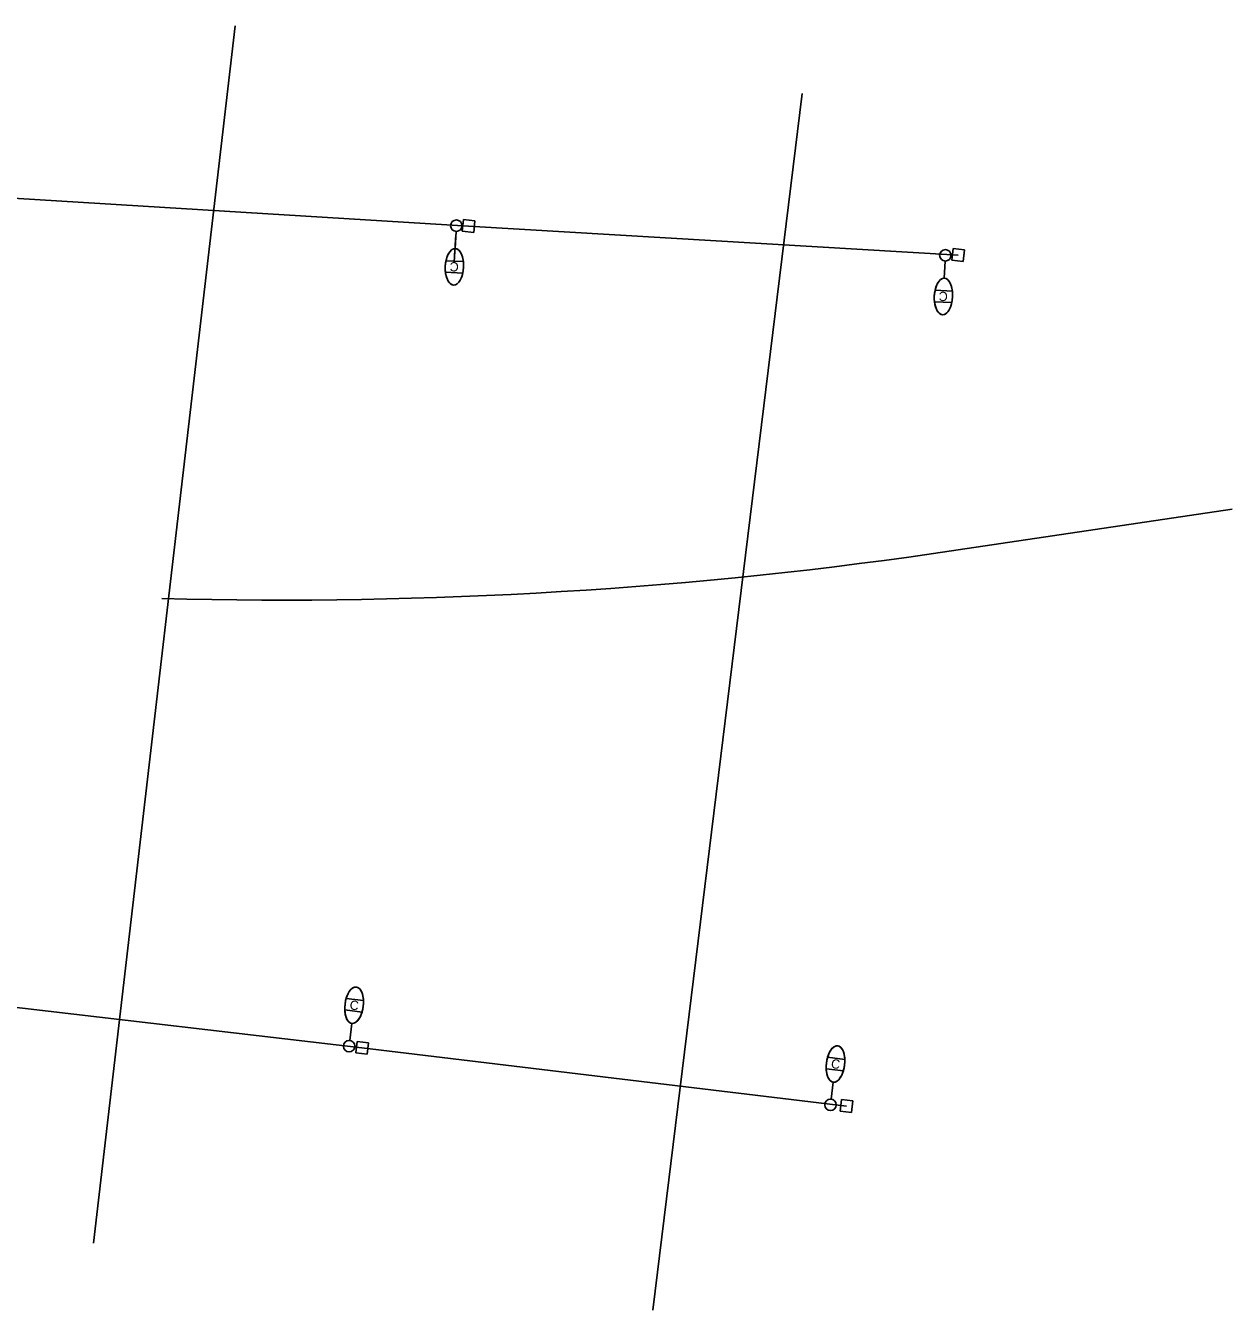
# Model space of a CAD drawing. Extents: x 915723 to 927758, y 636394 to 638609.
# Drawn here: x 927236 to 927758, y 636394 to 636950 of the extents above; entities that cross this region are included whole.
import ezdxf

# ---------------------------------------------------------------- set-up
doc = ezdxf.new("R2010")
doc.units = 0
for name, color, linetype in [('ConduitOT', 7, 'Continuous'), ('DrShaftConc', 7, 'Continuous'), ('Masonry_h', 7, 'Continuous'), ('Miscellaneous2', 7, 'Continuous'), ('PoleLight', 7, 'Continuous'), ('PullBox', 7, 'Continuous'), ('TextStructuresLabel', 7, 'Continuous')]:
    doc.layers.add(name, color=color, linetype=linetype)

msp = doc.modelspace()

# ---------------------------------------------------------------- linework, layer by layer
at = {"layer": 'ConduitOT'}
for p, q in [((927427.58, 636863), (927217.6, 636875.85)), ((927639.56, 636850.45), (927427.58, 636863)), ((927381.44, 636507.28), (927172.16, 636531.7)), ((927591.21, 636482.09), (927381.44, 636507.28))]:
    msp.add_line(p, q, dxfattribs=at)
at = {"layer": 'DrShaftConc'}
for p, q in [((927326.5, 636949.72), (927265.15, 636422.71)), ((927572.13, 636920.31), (927507.34, 636393.71)), ((927758.35, 636740.53), (927639.67, 636722.81)), ((927639.67, 636722.81), (927758.35, 636740.53))]:
    msp.add_line(p, q, dxfattribs=at)
msp.add_arc((927347.51, 638679.45), 1978.34, 268.47316, 278.49255, dxfattribs=at)
msp.add_arc((927347.51, 638679.45), 1978.34, 268.47316, 278.49255, dxfattribs=at)
at = {"layer": 'Masonry_h'}
for p, q in [((927422.1, 636859.34), (927421.38, 636847.36)), ((927421.92, 636856.35), (927421.56, 636850.36))]:
    msp.add_line(p, q, dxfattribs=at)
at = {"layer": 'Miscellaneous2'}
for p, q in [((927425.34, 636847.67), (927417.83, 636848.02)), ((927417.83, 636848.02), (927417.83, 636848.02)), ((927417.6, 636843.03), (927417.6, 636843.03)), ((927417.6, 636843.03), (927425.1, 636842.67)), ((927637.12, 636834.85), (927629.61, 636835.21)), ((927629.61, 636835.21), (927629.61, 636835.21)), ((927629.37, 636830.22), (927629.37, 636830.22)), ((927629.37, 636830.22), (927636.88, 636829.86)), ((927382.06, 636527.76), (927374.61, 636528.68)), ((927382.06, 636527.76), (927382.06, 636527.76)), ((927373.99, 636523.72), (927381.45, 636522.8)), ((927381.45, 636522.8), (927381.45, 636522.8)), ((927590.53, 636502.33), (927583.07, 636503.25)), ((927590.53, 636502.33), (927590.53, 636502.33)), ((927582.46, 636498.29), (927589.92, 636497.37)), ((927589.92, 636497.37), (927589.92, 636497.37))]:
    msp.add_line(p, q, dxfattribs=at)
for centre, major_axis, start_param, end_param in [((927421.47, 636845.35), (0.38, 7.91), 1.249648, 1.891946), ((927421.47, 636845.35), (0.38, 7.91), 4.391271, 5.033538), ((927421.47, 636845.35), (0.38, 7.91), 4.391241, 4.391271), ((927633.25, 636832.53), (0.38, 7.91), 1.249648, 1.891946), ((927633.25, 636832.53), (0.38, 7.91), 4.391271, 5.033538), ((927633.25, 636832.53), (0.38, 7.91), 4.391241, 4.391271), ((927378.03, 636525.74), (-0.97, -7.86), 4.391271, 5.033538), ((927378.03, 636525.74), (-0.97, -7.86), 4.391241, 4.391271), ((927378.03, 636525.74), (-0.97, -7.86), 1.249648, 1.891946), ((927586.5, 636500.31), (-0.97, -7.86), 4.391271, 5.033538), ((927586.5, 636500.31), (-0.97, -7.86), 4.391241, 4.391271), ((927586.5, 636500.31), (-0.97, -7.86), 1.249648, 1.891946)]:
    msp.add_ellipse(centre, major_axis=major_axis, ratio=0.5, start_param=start_param, end_param=end_param, dxfattribs=at)
at = {"layer": 'PoleLight'}
for p, q in [((927422.2, 636860.68), (927421.84, 636853.26)), ((927417.83, 636848.02), (927425.34, 636847.67)), ((927633.97, 636847.86), (927633.62, 636840.45)), ((927425.1, 636842.67), (927417.6, 636843.03)), ((927629.61, 636835.21), (927637.12, 636834.85)), ((927636.88, 636829.86), (927629.37, 636830.22)), ((927374.61, 636528.68), (927382.06, 636527.76)), ((927381.45, 636522.8), (927373.99, 636523.72)), ((927376.16, 636510.51), (927377.06, 636517.88)), ((927583.07, 636503.25), (927590.53, 636502.33)), ((927589.92, 636497.37), (927582.46, 636498.29)), ((927584.63, 636485.08), (927585.53, 636492.45))]:
    msp.add_line(p, q, dxfattribs=at)
for centre in [(927422.32, 636863.15), (927422.32, 636863.15), (927634.09, 636850.33), (927634.09, 636850.33), (927375.85, 636508.05), (927375.85, 636508.05), (927584.32, 636482.62), (927584.32, 636482.62)]:
    msp.add_circle(centre, 2.48, dxfattribs=at)
for centre, major_axis in [((927421.47, 636845.35), (0.38, 7.91)), ((927633.25, 636832.53), (0.38, 7.91)), ((927378.03, 636525.74), (-0.97, -7.86)), ((927586.5, 636500.31), (-0.97, -7.86))]:
    msp.add_ellipse(centre, major_axis=major_axis, ratio=0.5, dxfattribs=at)
for centre, major_axis, start_param, end_param in [((927421.47, 636845.35), (0.38, 7.91), 0.847605, 1.249648), ((927421.47, 636845.35), (0.38, 7.91), 0, 0.847605), ((927421.47, 636845.35), (0.38, 7.91), 5.033538, 6.283185), ((927421.47, 636845.35), (0.38, 7.91), 1.891945, 4.391241), ((927633.25, 636832.53), (0.38, 7.91), 0, 0.847605), ((927633.25, 636832.53), (0.38, 7.91), 5.033538, 6.283185), ((927633.25, 636832.53), (0.38, 7.91), 0.847605, 1.249648), ((927633.25, 636832.53), (0.38, 7.91), 1.891945, 4.391241), ((927378.03, 636525.74), (-0.97, -7.86), 1.891945, 4.391241), ((927378.03, 636525.74), (-0.97, -7.86), 5.033538, 6.283185), ((927378.03, 636525.74), (-0.97, -7.86), 0.847605, 1.249648), ((927378.03, 636525.74), (-0.97, -7.86), 0, 0.847605), ((927586.5, 636500.31), (-0.97, -7.86), 1.891945, 4.391241), ((927586.5, 636500.31), (-0.97, -7.86), 5.033538, 6.283185), ((927586.5, 636500.31), (-0.97, -7.86), 0, 0.847605), ((927586.5, 636500.31), (-0.97, -7.86), 0.847605, 1.249648)]:
    msp.add_ellipse(centre, major_axis=major_axis, ratio=0.5, start_param=start_param, end_param=end_param, dxfattribs=at)
at = {"layer": 'PullBox'}
for p, q in [((927424.84, 636860.84), (927425.41, 636865.81)), ((927425.41, 636865.81), (927430.38, 636865.24)), ((927430.38, 636865.24), (927429.81, 636860.27)), ((927429.81, 636860.27), (927424.84, 636860.84)), ((927636.84, 636848.29), (927637.42, 636853.26)), ((927637.42, 636853.26), (927642.38, 636852.69)), ((927642.38, 636852.69), (927641.81, 636847.72)), ((927641.81, 636847.72), (927636.84, 636848.29)), ((927378.72, 636505.13), (927379.3, 636510.09)), ((927379.3, 636510.09), (927384.26, 636509.52)), ((927384.26, 636509.52), (927383.69, 636504.55)), ((927383.69, 636504.55), (927378.72, 636505.13)), ((927588.49, 636479.94), (927589.06, 636484.9)), ((927589.06, 636484.9), (927594.03, 636484.33)), ((927594.03, 636484.33), (927593.46, 636479.36)), ((927593.46, 636479.36), (927588.49, 636479.94))]:
    msp.add_line(p, q, dxfattribs=at)

# ---------------------------------------------------------------- texts
at = {"layer": 'TextStructuresLabel'}
for rotation, p in [(177.277, (927423.43, 636847.26)), (177.277, (927635.21, 636834.44)), (352.985, (927375.93, 636523.98)), (352.985, (927584.4, 636498.55))]:
    msp.add_text('C', height=4, rotation=rotation, dxfattribs=at).set_placement(p)

doc.saveas('drawing.dxf')
